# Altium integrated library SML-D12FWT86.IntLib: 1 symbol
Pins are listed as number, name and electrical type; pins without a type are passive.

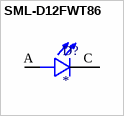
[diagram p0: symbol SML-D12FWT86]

## SML-D12FWT86
designator D?
Orange 605nm LED Indication - Discrete 2.2V 0603 (1608 Metric); MP: SML-D12FWT86
footprint LED_SML-D12FWT86
pins: A, C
